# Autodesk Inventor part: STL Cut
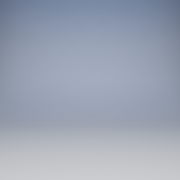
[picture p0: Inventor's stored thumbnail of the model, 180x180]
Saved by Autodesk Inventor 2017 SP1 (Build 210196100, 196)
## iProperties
Created: 2016-12
Part Number: STL Cut
Material: Generic
Document SubType Name: Modeling
Designer: HP_ELITE
Density: 1 g/cm^3
Appearance: Default
Author: HP_ELITE
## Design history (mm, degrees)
sketch "Sketch1"
  geometry: C1 r 1.75 at (0, -33) reference; C2 r 1.75 at (-28.579, 16.5) reference; C3 r 1.75 at (28.579, 16.5) reference; 1 further point
extrude "Extrusion1" new body sketch "Sketch1" distance "d0" = 3; taper "d2" = 0 deg; dims "d1" = 5, "d3" = 0
sketch "Sketch2"
  geometry: L1 (0, 3.291)-(2.85, 1.645); L2 (2.85, 1.645)-(2.85, -1.645); L3 (2.85, -1.645)-(0, -3.291); L4 (0, -3.291)-(-2.85, -1.645); L5 (-2.85, -1.645)-(-2.85, 1.645); L6 (-2.85, 1.645)-(0, 3.291); L7 (57.158, 3.291)-(60.008, 1.645); L8 (60.008, 1.645)-(60.008, -1.645); L9 (60.008, -1.645)-(57.158, -3.291); L10 (57.158, -3.291)-(54.308, -1.645); L11 (54.308, -1.645)-(54.308, 1.645); L12 (54.308, 1.645)-(57.158, 3.291); L13 (28.579, -46.209)-(31.429, -47.855); L14 (31.429, -47.855)-(31.429, -51.145); L15 (31.429, -51.145)-(28.579, -52.791); L16 (28.579, -52.791)-(25.729, -51.145); L17 (25.729, -51.145)-(25.729, -47.855); L18 (25.729, -47.855)-(28.579, -46.209); C1 r 1.75 at (57.158, 0) reference; C2 r 1.75 at (28.579, -49.5) reference; C3 r 1.75 at (0, 0) reference; 4 further points
  constraints: 36 end point, 3 coincident, 3 vertical, 2 parallel, 39 other
  dimensions: "d4" = 5.7 distance between parallel lines of L2 L5
extrude "Extrusion2" join sketch "Sketch2" distance "d5" = 7; taper "d6" = 0 deg
body "Solid1"
node "Reference1"
node "Reference2"
node "Reference3"
